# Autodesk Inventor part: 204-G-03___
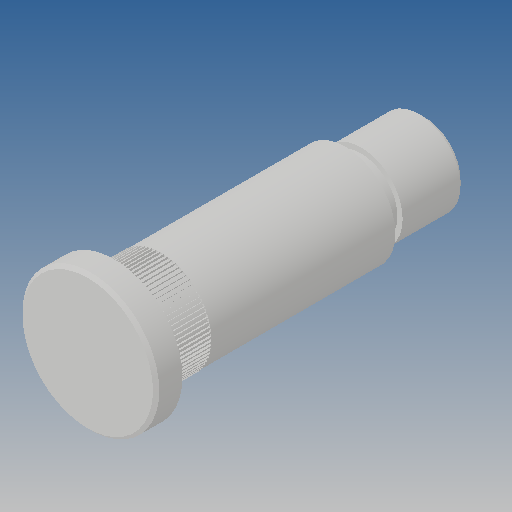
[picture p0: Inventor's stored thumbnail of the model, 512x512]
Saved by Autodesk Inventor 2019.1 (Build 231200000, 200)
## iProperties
Created: 2010-06
Part Number: 204-G-03___
Material: Ogólny
Document SubType Name: Modeling
Designer: CADENGINEERING4
Density: 1 g/cm^3
Appearance: Domyślna
Author: CADENGINEERING4
Revision Number: ANY
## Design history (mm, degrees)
feature "NONE"
node "Bryła1"
